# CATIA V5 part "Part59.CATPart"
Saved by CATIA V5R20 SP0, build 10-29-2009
Part number: 9AE103036-2
Revision: ANY
Definition: UNKNOWN
Nomenclature: 9AE103036-2
Source: Unknown
Bounding box of the stored display mesh (mm): x -20 to 20, y -20 to 20, z 0 to 62
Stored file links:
  C:\Users\Utente\Desktop\IO LAVORO\3D X SITO CF\CUMSA\3D files AE\Part59.CATPart
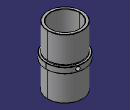
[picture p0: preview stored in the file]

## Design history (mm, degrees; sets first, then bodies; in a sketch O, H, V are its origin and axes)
Body1 "Cortar-Extruir2" (main body)
  Solid1: solid without history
